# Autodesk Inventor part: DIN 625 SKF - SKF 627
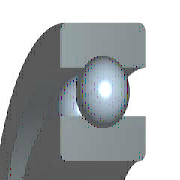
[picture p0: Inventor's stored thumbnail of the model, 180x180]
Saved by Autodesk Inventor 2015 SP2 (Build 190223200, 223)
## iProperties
IsCustomPart: 0
Created: 2012-02
Part Number: DIN 625 SKF - SKF 627
Material: Stahl, weich
Description: Kugellager, einreihig
Document SubType Name: Modeling
Standard: DIN 625
Designer: rYan
Standards Organization: DIN
Language: de-DE
Size Designation: SKF 627
Categories: <MemberInstance><Categories><Category DisplayName="Wellenteile" InternalName="7f7aeb1f-a693-4053-b835-cee3144e0d98" Mnemonic="SHFT"><Category DisplayName="Lager
Density: 7.85 g/cm^3
Mass: 12.2408 g
Surface Area: 20.5713 cm^2
Volume: 1.55934 cm^3
Appearance: Halbpoliert
Author: rYan
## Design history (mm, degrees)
node "WorkPoint1"
revolve "Drehung1" stored, may be unused: angle "d6" = 360 deg
node "WorkAxis1"
node "WorkPlane3"
revolve "Drehung2" stored, may be unused: angle "d10" = 360 deg
node "WorkPlane4"
node "WorkPoint2"
sketch "Skizze5"
  geometry: L1 (7.25, 1.25)-(7.25, 5.75); L2 (8.6, 0)-(-8.6, 0) reference; L3 (7.25, 1.25)-(7.25, 5.75); A1 r 2.25 centre (7.25, 3.5) between (7.25, 1.25) and (7.25, 5.75); A2 r 2.25 centre (7.25, 3.5) between (8.6, 1.7) and (8.6, 5.3) reference
  constraints: 4 end point, 2 point on circle, 1 centre point, 1 concentric, 1 vertical
  dimensions: "d13" = 0 horizontal distance of A1.centre L1.start; "d15" = 4.5001 diameter of A1 (computed from msp_mdtd6)
revolve "Drehung3" sketch "Skizze5" stored, may be unused: angle "d16" = 360 deg
pattern_circular "Polare Anordnung1" dims "d17" = 52.33333 (= msp_pocet), angle "d19" = 360 deg
body "Solid1"
node "Skizze1"
node "Skizze4"
fillet "Rundung1" dims "d20" = 0.3 (= r)
sketch "Skizze2"
  geometry: L1 (3.5, 7)-(11, 7); L2 (3.5, 0)-(3.5, 7); L3 (11, 0)-(3.5, 0); L4 (11, 7)-(11, 0); L5 (0, 0)-(0, 20); L6 (0, 0)-(0, 20); L7 (-2.2, 0)-(13.2, 0) reference
  constraints: 12 end point, 3 vertical, 2 horizontal, 1 collinear, 1 other
  dimensions: "d1" = 7 vertical distance of L1.start L5 (= Diam); "d3" = 22 diameter of L1.end L5 (= DD); "d5" = 7 distance of L2.start L1.start (= msp_mdtd2)
sketch "Skizze3"
  geometry: L1 (8.6, 7)-(8.6, 5.3); L2 (5.9, 7)-(8.6, 7); L3 (5.9, 5.3)-(5.9, 7); L4 (5.9, 0)-(5.9, 1.7); L5 (8.6, 0)-(5.9, 0); L6 (8.6, 1.7)-(8.6, 0); L7 (11, 0)-(-11, 0) reference; L8 (11, 7)-(-11, 7) reference; L9 (0, -42.29)-(0, 61.29); L10 (0, 82.007)-(0, -63.007) reference; A1 r 2.25 centre (7.25, 3.5) between (8.6, 1.7) and (8.6, 5.3); A2 r 2.25 centre (7.25, 3.5) between (5.9, 5.3) and (5.9, 1.7)
  constraints: 14 end point, 4 collinear, 4 point on circle, 4 vertical, 2 centre point, 2 concentric, 2 horizontal, 2 point on line
  dimensions: "d9" = 4.5 diameter of A1 (= msp_mdtd6); "d21" = 5.9 distance between parallel lines of L9 L4 (= 0.5 x msp_d1); "d22" = 7.25 distance from line of L9 A1.centre (= 0.5 x msp_ds); "d23" = 8.6 distance between parallel lines of L9 L6 (= 0.5 x msp_dd1)
other parameters: "Diam" = 7 [user parameter; used in 3 equation terms], "DD" = 22 [user parameter; used in 3 equation terms], "B" = 7 [user parameter; used in 1 equation term], "r" = 0.3 [user parameter; used in 1 equation term], "msp_ds" = 14.5 (= 0.5 x Diam + 0.5 x DD) [user parameter; used in 5 equation terms], "msp_d0" = 4.5 (= -0.3 x Diam + 0.3 x DD) [user parameter; used in 4 equation terms], "msp_d1" = 11.8 (= msp_ds - 0.6 x msp_d0) [user parameter; used in 1 equation term], "msp_dd1" = 17.2 (= msp_ds + 0.6 x msp_d0) [user parameter; used in 1 equation term], "msp_pom" = 21.75 (= 1.5 x msp_ds) [user parameter; used in 1 equation term], "msp_mdtd2" = 7 (= B) [user parameter; used in 3 equation terms], "msp_mdtd4" = 14.5 (= msp_ds) [user parameter], "msp_mdtd6" = 4.5 (= msp_d0) [user parameter; used in 2 equation terms], "msp_mdtd7" = 3.5 (= 0.5 x msp_mdtd2) [user parameter], "msp_pocet" = 52.33333 (computed from msp_d0, msp_pom) [user parameter; used in 1 equation term], "d2" = 72 (derived), "d4" = 19 (derived), "d7" = 0, "d8" = 15.6 (derived), "d11" = -7 (computed from msp_mdtd2), "d12" = 0 (derived), "d14" = 15.6001 (derived), "d26" = 0, "d27" = 0, "d28" = 0, "d29" = 0, "d30" = 0
